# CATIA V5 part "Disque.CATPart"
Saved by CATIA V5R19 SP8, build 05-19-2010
Part number: Disque
Bounding box of the stored display mesh (mm): x -15 to 0, y -40.5 to 40.5, z -40.5 to 40.5
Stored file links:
  C:\Users\ThinkMotion\Desktop\EU_thinkMotion\iao\IAO_MMS_Groupe3\pmayet\pmayet_avant_optimisation\pmayet_avant_optimisation\Disque.CATPart
  C:\Users\ThinkMotion\Desktop\EU_thinkMotion\iao\IAO_MMS_Groupe3\pmayet\pmayet_avant_optimisation\pmayet_avant_optimisation\pmayet.CATProduct
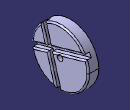
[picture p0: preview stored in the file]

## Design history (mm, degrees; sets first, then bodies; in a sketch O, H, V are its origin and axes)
Parameters
  Rayon_disque = 40.5 mm
  Largeur_rainure_a = 6 mm
  Largeur_rainure_b = 5 mm
  Epaisseur_disque = 15 mm
  Rayon_arbre_bati = 4 mm
Set1
  Plane1: linked copy from another document
  Point1 "PointA": linked copy from another document
  Line1: linked copy from another document
  Line2: linked copy from another document
Body1 (main body)
  Sketch1 on Plane1, origin (0, 0, 0), H (0, 1, 0), V (0, 0, 1)
    circle A1 centre (0, 0) radius 40.5
    point P1 (0, 0)
    reference projected point E1 (0, 0) from Point1
    distance A1 P1 = 40.5 {= Rayon_disque}
    coincidence: E1 P1
  Pad1: profile Sketch1, direction (-1, 0, 0), length 15 {= Epaisseur_disque}
  Sketch2 on Plane1, origin (0, 0, 0), H (0, 1, 0), V (0, 0, 1)
    line L1 (-40.4975, -0.4507) -> (-18.5487, 5.8204)
    point P1 (-40.4975, -0.4507)
    point P2 (-18.5487, 5.8204)
    line L2 (-39.9685, -6.5396) -> (-16.9004, 0.0513)
    point P3 (-39.9685, -6.5396)
    point P4 (-16.9004, 0.0513)
    line L3 (-25.8044, 31.2151) -> (-18.5487, 5.8204)
    point P5 (-25.8044, 31.2151)
    point P6 (-18.5487, 5.8204)
    line L4 (-21.4932, 34.3263) -> (-13.7411, 7.194)
    point P7 (-21.4932, 34.3263)
    point P8 (-13.7411, 7.194)
    reference projected line E1 (-17.4944, 11.2305) -> (-6.5056, -27.2305) from Line1
    reference projected line E2 (-17.4944, 11.2305) -> (-6.5056, -27.2305) from Line1
    reference projected line E3 (-17.4944, 11.2305) -> (-6.5056, -27.2305) from Line1
    reference projected line E4 (-17.4944, 11.2305) -> (-6.5056, -27.2305) from Line1
    reference projected circle E5 centre (0, 0) radius 40.5 from edge [face of Pad1 from Sketch1.A1 | start face of Pad1]
    reference projected circle E6 centre (0, 0) radius 40.5 from edge [face of Pad1 from Sketch1.A1 | start face of Pad1]
    reference projected line E7 (-28, 0) -> (0, 8) from Line2
    reference projected line E8 (-28, 0) -> (0, 8) from Line2
    reference projected circle E9 centre (0, 0) radius 40.5 from edge [face of Pad1 from Sketch1.A1 | start face of Pad1]
    reference projected line E10 (-28, 0) -> (0, 8) from Line2
    reference projected line E11 (-28, 0) -> (0, 8) from Line2
    reference projected circle E12 centre (0, 0) radius 40.5 from edge [face of Pad1 from Sketch1.A1 | start face of Pad1]
    line L5 (-16.9004, 0.0513) -> (-5.4183, -40.1359)
    point P9 (-16.9004, 0.0513)
    point P10 (-5.4183, -40.1359)
    line L6 (-12.0928, 1.4249) -> (-0.1143, -40.4998)
    point P11 (-12.0928, 1.4249)
    point P12 (-0.1143, -40.4998)
    line L7 (-13.7411, 7.194) -> (34.6228, 21.0123)
    point P13 (-13.7411, 7.194)
    point P14 (34.6228, 21.0123)
    line L8 (-12.0928, 1.4249) -> (37.3904, 15.5629)
    point P15 (-12.0928, 1.4249)
    point P16 (37.3904, 15.5629)
    reference projected line E13 (-17.4944, 11.2305) -> (-6.5056, -27.2305) from Line1
    reference projected line E14 (-17.4944, 11.2305) -> (-6.5056, -27.2305) from Line1
    reference projected line E15 (-17.4944, 11.2305) -> (-6.5056, -27.2305) from Line1
    reference projected line E16 (-17.4944, 11.2305) -> (-6.5056, -27.2305) from Line1
    reference projected circle E17 centre (0, 0) radius 40.5 from edge [face of Pad1 from Sketch1.A1 | start face of Pad1]
    reference projected circle E18 centre (0, 0) radius 40.5 from edge [face of Pad1 from Sketch1.A1 | start face of Pad1]
    reference projected line E19 (-28, 0) -> (0, 8) from Line2
    reference projected line E20 (-28, 0) -> (0, 8) from Line2
    reference projected line E21 (-28, 0) -> (0, 8) from Line2
    reference projected line E22 (-28, 0) -> (0, 8) from Line2
    reference projected circle E23 centre (0, 0) radius 40.5 from edge [face of Pad1 from Sketch1.A1 | start face of Pad1]
    reference projected circle E24 centre (0, 0) radius 40.5 from edge [face of Pad1 from Sketch1.A1 | start face of Pad1]
    arc A1 centre (0, 0) radius 40.5 from (-21.4932, 34.3263) to (-25.8044, 31.2151) ccw
    point P17 (0, 0)
    point P18 (-21.4932, 34.3263)
    point P19 (-25.8044, 31.2151)
    reference projected point E25 (0, 0) from Point1
    arc A2 centre (0, 0) radius 40.5 from (37.3904, 15.5629) to (34.6228, 21.0123) ccw
    point P20 (0, 0)
    point P21 (37.3904, 15.5629)
    point P22 (34.6228, 21.0123)
    reference projected point E26 (0, 0) from Point1
    arc A3 centre (0, 0) radius 40.5 from (-40.4975, -0.4507) to (-39.9685, -6.5396) ccw
    point P23 (0, 0)
    point P24 (-40.4975, -0.4507)
    point P25 (-39.9685, -6.5396)
    reference projected point E27 (0, 0) from Point1
    arc A4 centre (0, 0) radius 40.5 from (-5.4183, -40.1359) to (-0.1143, -40.4998) ccw
    point P26 (0, 0)
    point P27 (-5.4183, -40.1359)
    point P28 (-0.1143, -40.4998)
    reference projected point E28 (0, 0) from Point1
    distance L3 E1 = 2.5 {= Largeur_rainure_b /2}
    distance L4 E3 = 2.5 {= Largeur_rainure_b /2}
    distance L1 E7 = 3 {= Largeur_rainure_a /2}
    distance L2 E10 = 3 {= Largeur_rainure_a /2}
    distance L6 E13 = 2.5 {= Largeur_rainure_b /2}
    distance L5 E15 = 2.5 {= Largeur_rainure_b /2}
    distance E19 L7 = 3 {= Largeur_rainure_a /2}
    distance E21 L8 = 3 {= Largeur_rainure_a /2}
    parallelism: L3 E2, L4 E4, L1 E8, L2 E11, L6 E14, L5 E16, E20 L7, E22 L8
    coincidence: E5 P7, E6 P5, E9 P1, P2 P6, E12 P3, E17 P10, E18 P12, P4 P9, P11 P15, P8 P13, P14 E23, P16 E24, P17 E25, P18 P7, P19 P5, P20 E26, P14 P22, P16 P21, P23 E27, P1 P24, P3 P25, P26 E28, P27 P10, P12 P28
  Pocket1: profile Sketch2, direction (-1, 0, 0), length 7.5 {= Epaisseur_disque /2}
  Fillet1: radius 2, on start face of Pad1
  Fillet2: radius 2, on start face of Pad1
  Fillet3: radius 2, on start face of Pad1
  Fillet4: radius 2, on start face of Pad1
  Sketch3 on Plane1, origin (0, 0, 0), H (0, 1, 0), V (0, 0, 1)
    circle A1 centre (0, 0) radius 4
    point P1 (0, 0)
    reference projected point E1 (0, 0) from Point1
    distance A1 P1 = 4 {= Rayon_arbre_bati}
    coincidence: E1 P1
  Pocket2: profile Sketch3, direction (-1, 0, 0), length 15 {= Epaisseur_disque}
